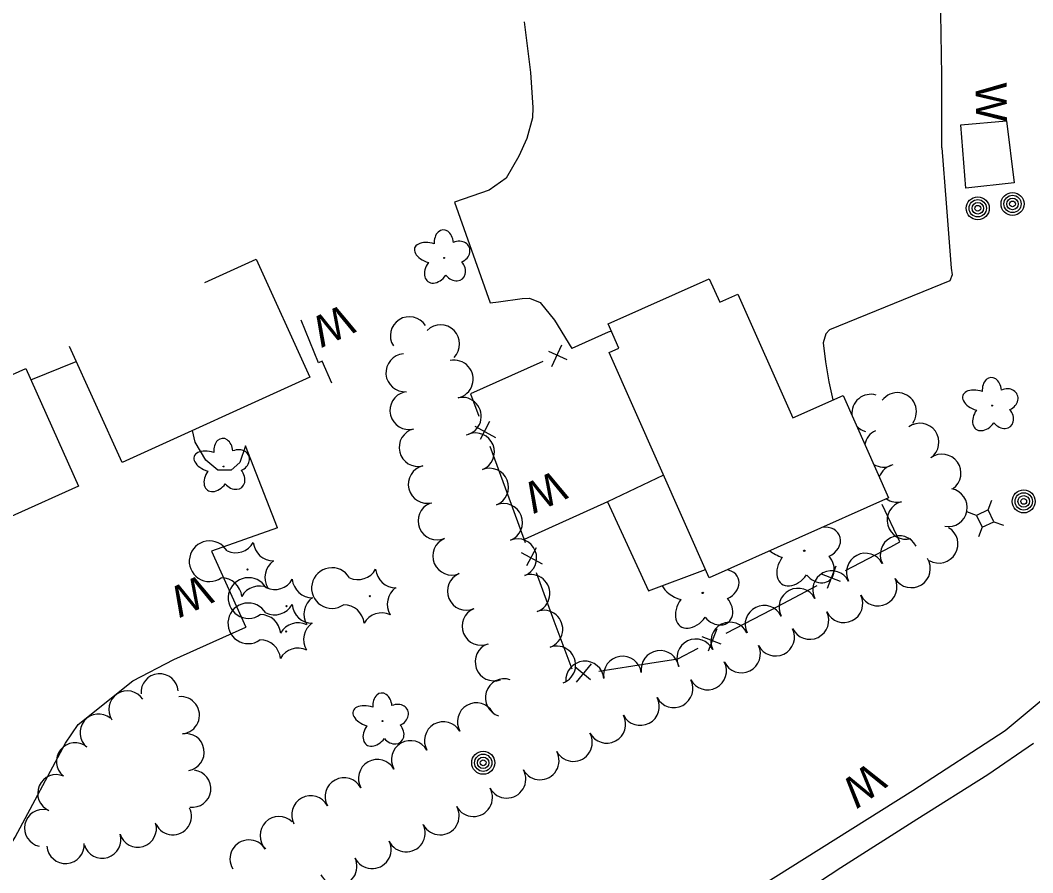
# Model space of a CAD drawing. Extents: x 588843 to 2552415, y 180129 to 269402.
# Drawn here: x 593585.5 to 593781.7, y 188224.6 to 188389.7 of the extents above; entities that cross this region are included whole.
import ezdxf

# ---------------------------------------------------------------- set-up
doc = ezdxf.new("R2010")
doc.units = 0
for name, color, linetype in [('Default', 7, 'Continuous'), ('E_BLD', 7, 'Continuous'), ('E_BLD_HvyDash', 7, 'Continuous'), ('E_DWY', 7, 'Continuous'), ('E_FEN_P', 7, 'Continuous'), ('E_LAND_TreeLine_P', 7, 'Continuous'), ('E_LAND_Vegetation', 7, 'Continuous'), ('E_MISCPROP', 7, 'Continuous'), ('E_RDWY', 7, 'Continuous'), ('E_RDWY_Gravel', 7, 'Continuous'), ('E_UTL_AG_Bold', 7, 'Continuous'), ('E_WAL', 7, 'Continuous'), ('E_WAL_Text', 7, 'Continuous')]:
    doc.layers.add(name, color=color, linetype=linetype)

# ---------------------------------------------------------------- blocks, each defined once
blk = doc.blocks.new('PED')
at = {"layer": 'Default'}
for p, q in [((-2.5, 2.5), (-5.33, 5.33)), ((2.5, 2.5), (5.33, 5.33)), ((-2.5, -2.5), (-5.33, -5.33)), ((2.5, -2.5), (5.33, -5.33))]:
    blk.add_line(p, q, dxfattribs=at)
blk.add_lwpolyline([(-2.5, -2.5), (2.5, -2.5), (2.5, 2.5), (-2.5, 2.5)], close=True, dxfattribs=at)
blk = doc.blocks.new('POLE')
at = {"layer": 'Default'}
for radius in [4.46, 3.35, 2.23, 1.12]:
    blk.add_circle((0, 0), radius, dxfattribs=at)
blk = doc.blocks.new('W_23')
at = {"layer": 'E_WAL_Text'}
blk.add_text('W', height=12, dxfattribs=at).set_placement((-4.46, -6))
blk = doc.blocks.new('W_24')
at = {"layer": 'E_WAL_Text'}
blk.add_text('W', height=12, dxfattribs=at).set_placement((-4.46, -6))
blk = doc.blocks.new('DTRE')
at = {"layer": 'Default'}
blk.add_circle((-0.18, 0), 0.183, dxfattribs=at)
for centre, major_axis, ratio in [((-1.87, 5.32), (1.36, -4.98), 0.782863), ((4.06, 2.74), (-5.27, -2.93), 0.691916), ((-5.87, 0.15), (4.93, -0.12), 0.832022), ((3.54, -3.71), (-5.01, 4.58), 0.560249), ((-2.49, -5.24), (1.8, 4.86), 0.716896)]:
    blk.add_ellipse(centre, major_axis=major_axis, ratio=ratio, start_param=1.570796, end_param=4.712389, dxfattribs=at)
blk = doc.blocks.new('CTRE')
at = {"layer": 'Default'}
blk.add_circle((0, 0), 0.223, dxfattribs=at)
for centre, start, end in [((-11.97, 8.96), 280.2067, 5.9716), ((1.81, 14.92), 220.2113, 305.9762), ((13.83, 5.89), 160.2113, 245.9762), ((-13.83, -5.9), 340.2113, 65.9762), ((12.03, -9.04), 185.9272, 100.2511), ((-1.81, -14.93), 40.2113, 125.9762)]:
    blk.add_arc(centre, 7.87, start, end, dxfattribs=at)
blk = doc.blocks.new('W_27')
at = {"layer": 'E_WAL_Text'}
blk.add_text('W', height=12, dxfattribs=at).set_placement((-4.46, -6))
blk = doc.blocks.new('U298')
at = {"layer": 'E_LAND_Vegetation'}
blk.add_circle((0.09, 0.03), 0.128, dxfattribs=at)
for centre, major_axis, ratio, start_param, end_param in [((3.75, 1.6), (-3.17, -1.37), 0.832022, 1.570796, 4.433022), ((-3.37, 1.29), (4.53, -1.44), 0.560249, 4.111817, 4.712389), ((-1.81, -2.95), (2.49, 3.41), 0.691916, 1.570796, 4.712389), ((2.72, -2.86), (-2.33, 2.77), 0.782863, 1.570796, 4.712389)]:
    blk.add_ellipse(centre, major_axis=major_axis, ratio=ratio, start_param=start_param, end_param=end_param, dxfattribs=at)

msp = doc.modelspace()

# ---------------------------------------------------------------- linework, layer by layer
at = {"layer": 'E_BLD'}
msp.add_lwpolyline([(593621.29, 188338.9), (593631.23, 188343.41), (593641.62, 188320.53), (593605.25, 188304), (593595.05, 188326.47)], dxfattribs=at)
for points in [[(593724.53, 188336.6), (593735.17, 188312.67), (593744.91, 188317), (593753.74, 188297.16), (593718.98, 188281.69), (593699.57, 188325.32), (593701.49, 188326.18), (593699.39, 188330.89), (593719, 188339.61), (593721.03, 188335.04), (593724.53, 188336.6)], [(593561.83, 188311.1), (593586.61, 188322.2), (593596.81, 188299.42), (593572.04, 188288.32), (593561.83, 188311.1)]]:
    msp.add_lwpolyline(points, close=True, dxfattribs=at)
at = {"layer": 'E_BLD_HvyDash'}
msp.add_lwpolyline([(593710.14, 188301.57), (593699.27, 188296.42), (593707.19, 188279.14), (593718.28, 188283.28)], dxfattribs=at)
at = {"layer": 'E_DWY'}
for points in [[(593764.07, 188364.94), (593764.07, 188378.97), (593763.83, 188391), (593763.04, 188399.28), (593759.94, 188404.55), (593757.36, 188412.22), (593755.89, 188417.04), (593754.97, 188421.78), (593754.11, 188435.35), (593753.88, 188443.08), (593753.75, 188451.7), (593753.06, 188460.33), (593752.81, 188462.25)], [(593683.11, 188389.39), (593684.39, 188379.56), (593684.82, 188372.77), (593684.77, 188370.75), (593683.64, 188366.79), (593682.08, 188363.36), (593679.66, 188359.11), (593676.36, 188356.76), (593669.61, 188354.41), (593676.57, 188334.95), (593678.19, 188335.13), (593682.73, 188335.75), (593684.19, 188335.84), (593686.26, 188334.98), (593689.02, 188331.61), (593692.36, 188326.08)], [(593764.07, 188364.94), (593764.88, 188354.23), (593765.86, 188341.64), (593766.06, 188340.38), (593765.62, 188339.18), (593742.3, 188329.68), (593741.58, 188328.94), (593741.05, 188327.17), (593741.48, 188323.5), (593742.13, 188319.61), (593742.96, 188316.14)], [(593587.59, 188320.01), (593596.36, 188323.58)], [(593635.35, 188291.34), (593629.12, 188307.24), (593628.08, 188304.02), (593626.35, 188302.55), (593623.8, 188302.55), (593621.47, 188304.46), (593619.39, 188307.95), (593618.86, 188310.18)], [(593539.8, 188134.18), (593535.15, 188137.59), (593532.54, 188139.85), (593531.46, 188141.45), (593530.53, 188143.73), (593530.3, 188146.14), (593530.39, 188149.61), (593531.59, 188155.73), (593533.85, 188163.21), (593535.47, 188166.5), (593537.46, 188169.6), (593562.1, 188198.46), (593569.6, 188207.86), (593577.78, 188220.1), (593584.5, 188231.42), (593594.27, 188249.63), (593596.74, 188253.25), (593607.35, 188261.74), (593615.26, 188265.86), (593629.22, 188272.13)]]:
    msp.add_lwpolyline(points, dxfattribs=at)
at = {"layer": 'E_FEN_P'}
for p, q in [((593690.39, 188326.73), (593688.46, 188322.55)), ((593691.48, 188323.9), (593687.89, 188325.54)), ((593673.56, 188311.06), (593677.6, 188308.85)), ((593676.45, 188311.96), (593674.58, 188308.49)), ((593685.45, 188287.48), (593683.58, 188284.01)), ((593682.56, 188286.58), (593686.59, 188284.37)), ((593741.92, 188279.69), (593743.58, 188283.97)), ((593740.65, 188282.43), (593744.34, 188281.03)), ((593718.83, 188267.54), (593720.5, 188271.83)), ((593717.57, 188270.29), (593721.26, 188268.89)), ((593692.94, 188264.49), (593695.98, 188261.98)), ((593693.25, 188261.48), (593696.21, 188265.01))]:
    msp.add_line(p, q, dxfattribs=at)
for points in [[(593700.04, 188329.43), (593699.43, 188329.24), (593692.36, 188326.08)], [(593686.73, 188323.56), (593677.64, 188319.49)], [(593677.64, 188319.49), (593672.76, 188317.31), (593674.34, 188312.98)], [(593676.47, 188307.2), (593679.91, 188297.85)], [(593679.91, 188297.85), (593683.34, 188288.5)], [(593754.18, 188287.71), (593755.91, 188288.63), (593752.51, 188295.87)], [(593745.37, 188283.08), (593754.18, 188287.71)], [(593685.47, 188282.72), (593688.91, 188273.37)], [(593731.1, 188275.57), (593739.91, 188280.21)], [(593722.28, 188270.93), (593731.1, 188275.57)], [(593688.91, 188273.37), (593692.34, 188264.02)], [(593707.45, 188265.14), (593712.92, 188266.01), (593716.83, 188268.06)], [(593697.61, 188263.58), (593707.45, 188265.14)]]:
    msp.add_lwpolyline(points, dxfattribs=at)
at = {"layer": 'E_LAND_TreeLine_P'}
for centre, radius, start, end in [((593660.9, 188328.56), 3.68, 32.3888, 212.3888), ((593666.95, 188326.99), 3.68, 314.7867, 134.7867), ((593660.03, 188321.39), 3.68, 94.4145, 274.4145), ((593669.58, 188320.15), 3.68, 282.2878, 102.2878), ((593660.81, 188314.08), 3.68, 103.993, 283.993), ((593671.14, 188312.95), 3.68, 282.2878, 102.2878), ((593750.29, 188313.54), 3.68, 73.4436, 186.0058), ((593755.45, 188313.86), 3.68, 323.2097, 143.2097), ((593750.29, 188313.54), 3.68, 221.968, 253.4436), ((593759.8, 188307.94), 3.68, 305.5239, 125.5239), ((593662.59, 188306.93), 3.68, 103.993, 283.993), ((593673.69, 188306.06), 3.68, 291.7282, 111.7282), ((593752.73, 188306.81), 3.68, 114.9064, 168.4593), ((593764.08, 188301.95), 3.68, 305.5239, 125.5239), ((593664.37, 188299.79), 3.68, 103.993, 283.993), ((593676.42, 188299.22), 3.68, 291.7282, 111.7282), ((593752.73, 188306.81), 3.68, 239.5145, 294.9064), ((593755.41, 188299.99), 3.68, 103.0992, 160.6595), ((593755.41, 188299.99), 3.68, 235.1707, 283.0992), ((593765.3, 188295.28), 3.68, 259.3478, 79.3478), ((593666.27, 188292.69), 3.68, 112.6907, 292.6907), ((593679.14, 188292.38), 3.68, 291.7282, 111.7282), ((593757.12, 188292.83), 3.68, 104.8791, 284.8791), ((593763.49, 188288.22), 3.68, 239.397, 59.397), ((593669.11, 188285.89), 3.68, 112.6907, 292.6907), ((593681.87, 188285.54), 3.68, 291.7282, 111.7282), ((593755.79, 188286.14), 3.68, 27.4238, 207.4238), ((593749.25, 188282.75), 3.68, 27.4238, 207.4238), ((593758.13, 188283.45), 3.68, 212.183, 32.183), ((593671.95, 188279.1), 3.68, 112.6907, 292.6907), ((593684.43, 188278.64), 3.68, 289.8544, 109.8544), ((593742.71, 188279.36), 3.68, 27.4238, 207.4238), ((593751.68, 188279.92), 3.68, 206.067, 26.067), ((593736.18, 188275.97), 3.68, 27.4238, 207.4238), ((593745.06, 188276.69), 3.68, 206.067, 26.067), ((593674.79, 188272.3), 3.68, 112.6907, 292.6907), ((593686.93, 188271.71), 3.68, 289.8544, 109.8544), ((593729.61, 188272.64), 3.68, 26.2082, 206.2082), ((593738.45, 188273.45), 3.68, 206.067, 26.067), ((593723, 188269.39), 3.68, 26.2082, 206.2082), ((593731.83, 188270.21), 3.68, 206.067, 26.067), ((593716.4, 188266.14), 3.68, 26.2082, 206.2082), ((593677.32, 188265.39), 3.68, 109.5704, 289.5704), ((593689.43, 188264.78), 3.68, 289.8544, 109.8544), ((593709.47, 188263.9), 3.68, 8.5636, 188.5636), ((593725.22, 188266.98), 3.68, 206.067, 26.067), ((593702.19, 188262.8), 3.68, 8.5636, 188.5636), ((593694.89, 188261.85), 3.68, 4.7174, 184.7174), ((593718.65, 188263.66), 3.68, 207.8694, 27.8694), ((593612.51, 188259.48), 3.61, 4.6314, 184.6314), ((593679.3, 188258.44), 3.68, 72.3808, 252.3808), ((593712.14, 188260.22), 3.68, 207.8694, 27.8694), ((593606.26, 188256.16), 3.61, 33.3345, 213.3345), ((593616.62, 188255.06), 3.61, 276.2104, 96.2104), ((593705.63, 188256.78), 3.68, 207.8694, 27.8694), ((593673.88, 188253.78), 3.68, 29.7728, 209.7728), ((593600.69, 188251.69), 3.61, 50.7851, 230.7851), ((593667.49, 188250.12), 3.68, 29.7728, 209.7728), ((593699.12, 188253.33), 3.68, 207.8694, 27.8694), ((593617.55, 188247.91), 3.61, 279.5641, 99.5641), ((593661.1, 188246.46), 3.68, 29.7728, 209.7728), ((593692.66, 188249.8), 3.68, 208.8688, 28.8688), ((593596.13, 188246.1), 3.61, 50.7851, 230.7851), ((593686.21, 188246.24), 3.68, 208.8688, 28.8688), ((593654.71, 188242.81), 3.68, 29.7728, 209.7728), ((593618.83, 188240.83), 3.61, 262.7506, 82.7506), ((593679.77, 188242.69), 3.68, 208.8688, 28.8688), ((593592.5, 188239.94), 3.61, 66.5223, 246.5223), ((593648.25, 188239.27), 3.68, 28.4408, 208.4408), ((593673.32, 188239.13), 3.68, 208.8688, 28.8688), ((593641.77, 188235.77), 3.68, 28.4408, 208.4408), ((593589.94, 188233.22), 3.61, 78.0882, 258.0882), ((593615.08, 188235.5), 3.61, 206.1794, 26.1794), ((593666.87, 188235.58), 3.68, 208.8688, 28.8688), ((593635.65, 188231.79), 3.68, 45.6607, 225.6607), ((593608.29, 188233.11), 3.61, 197.1882, 17.1882), ((593660.29, 188232.27), 3.68, 206.1033, 26.1033), ((593601.4, 188230.98), 3.61, 197.1882, 17.1882), ((593629.82, 188227.23), 3.68, 31.1415, 211.1415), ((593653.68, 188229.03), 3.68, 206.1033, 26.1033), ((593594.29, 188229.95), 3.61, 184.119, 4.119), ((593647.07, 188225.79), 3.68, 206.1033, 26.1033)]:
    msp.add_arc(centre, radius, start, end, dxfattribs=at)
at = {"layer": 'E_LAND_Vegetation'}
msp.add_circle((593717.74, 188278.74), 0.128, dxfattribs=at)
for centre, major_axis, ratio, start_param, end_param in [((593721.4, 188280.31), (-3.17, -1.37), 0.832022, 1.570796, 4.051342), ((593714.28, 188280), (4.53, -1.44), 0.560249, 3.609484, 4.712389), ((593715.85, 188275.75), (2.49, 3.41), 0.691916, 1.570796, 4.712389), ((593720.37, 188275.85), (-2.33, 2.77), 0.782863, 1.570796, 4.712389)]:
    msp.add_ellipse(centre, major_axis=major_axis, ratio=ratio, start_param=start_param, end_param=end_param, dxfattribs=at)
at = {"layer": 'E_RDWY'}
msp.add_lwpolyline([(593781.81, 188249.58), (593772.97, 188243.5), (593759.22, 188234.87), (593744.51, 188225.53), (593718.69, 188208.61), (593696.67, 188196.71), (593683.94, 188189.82), (593674.11, 188185.09), (593660.98, 188179.03), (593644.95, 188171.84), (593629.38, 188164.64), (593615.73, 188158.3), (593593.59, 188147.89), (593578.29, 188140.85)], dxfattribs=at)
at = {"layer": 'E_RDWY_Gravel'}
msp.add_lwpolyline([(593806.21, 188371.19), (593805.8, 188325.67), (593806.09, 188301.88), (593802.63, 188287.53), (593796.7, 188274.16), (593790.91, 188265.64), (593783.7, 188258.17), (593776.29, 188252.01), (593758.44, 188240.45), (593728.62, 188221.72), (593720.11, 188216.47), (593691.17, 188203.12), (593680.23, 188197.49)], dxfattribs=at)
at = {"layer": 'E_WAL'}
msp.add_lwpolyline([(593768.72, 188357.12), (593767.73, 188369.41), (593776.6, 188370.21), (593778.03, 188358.21), (593768.72, 188357.12)], close=True, dxfattribs=at)
for points in [[(593645.85, 188319.35), (593644, 188323.66), (593643.31, 188323.34), (593639.91, 188331.61)], [(593699.27, 188296.42), (593683.13, 188289.07)], [(593635.35, 188291.34), (593622.54, 188286.86), (593629.22, 188272.13)]]:
    msp.add_lwpolyline(points, dxfattribs=at)

# ---------------------------------------------------------------- block references
at = {"layer": 'E_LAND_Vegetation', "xscale": 0.5, "yscale": 0.5, "rotation": -155.21508863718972}
for name, p in [('DTRE', (593667.54, 188343.59)), ('DTRE', (593773.71, 188315)), ('DTRE', (593624.82, 188303.2)), ('CTRE', (593629.54, 188283.3)), ('CTRE', (593653.24, 188278.11)), ('CTRE', (593637.09, 188276.18)), ('CTRE', (593637.04, 188271.28)), ('DTRE', (593655.63, 188253.88))]:
    msp.add_blockref(name, p, dxfattribs=at)
at = {"layer": 'E_LAND_Vegetation'}
msp.add_blockref('U298', (593737.31, 188286.9), dxfattribs=at)
at = {"layer": 'E_MISCPROP'}
for p, xscale, yscale, rotation in [((593771.01, 188353.25), 0.5, 0.5, -155.21508863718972), ((593777.74, 188354.09), 0.49999999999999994, 0.49999999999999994, -154.79394034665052), ((593779.91, 188296.48), 0.49999999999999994, 0.49999999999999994, -154.79394034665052), ((593675.2, 188245.85), 0.5, 0.5, -155.21508863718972)]:
    msp.add_blockref('POLE', p, dxfattribs=dict(at, xscale=xscale, yscale=yscale, rotation=rotation))
at = {"layer": 'E_UTL_AG_Bold', "xscale": 0.49999999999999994, "yscale": 0.49999999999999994, "rotation": -154.79394034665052}
msp.add_blockref('PED', (593772.43, 188293.15), dxfattribs=at)
at = {"layer": 'E_WAL_Text'}
for name, p, xscale, yscale, rotation in [('W_23', (593773.61, 188375.35), 0.49999999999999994, 0.4999999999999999, -89.0813825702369), ('W_24', (593647.51, 188331.18), 0.5, 0.5, -155.21508863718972), ('W_24', (593688.61, 188299.01), 0.5, 0.5, -155.21508863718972), ('W_24', (593620.03, 188278.86), 0.5, 0.5, -155.21508863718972), ('W_27', (593750.18, 188242.49), 0.5, 0.49999999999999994, -143.48607765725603)]:
    msp.add_blockref(name, p, dxfattribs=dict(at, xscale=xscale, yscale=yscale, rotation=rotation))

doc.saveas('drawing.dxf')
